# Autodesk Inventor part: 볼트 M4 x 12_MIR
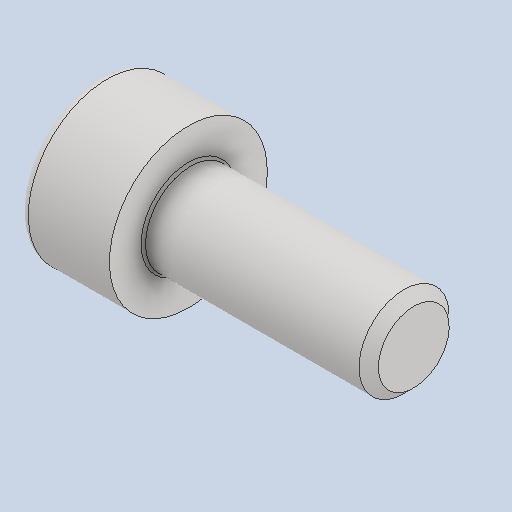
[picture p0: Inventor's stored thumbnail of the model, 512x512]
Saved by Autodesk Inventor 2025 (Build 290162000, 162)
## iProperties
Created: 2024-08
Part Number: 볼트 M4 x 12_MIR
Material: 스테인리스강
Description: 6각머리 태핑 나사
Document SubType Name: Modeling
Designer: SAMSUNG
Density: 8.08 g/cm^3
Appearance: 기본값
Author: jhkim
Sending System: Autodesk Inventor 2025
Preprocessor: ST-DEVELOPER v20
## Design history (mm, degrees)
derived "볼트 M4 x 12.ipt"
feature "솔리드1::볼트 M4 x 12.ipt" dims "d0" = 10
tag "피쳐 태그1"
node "솔리드1"
